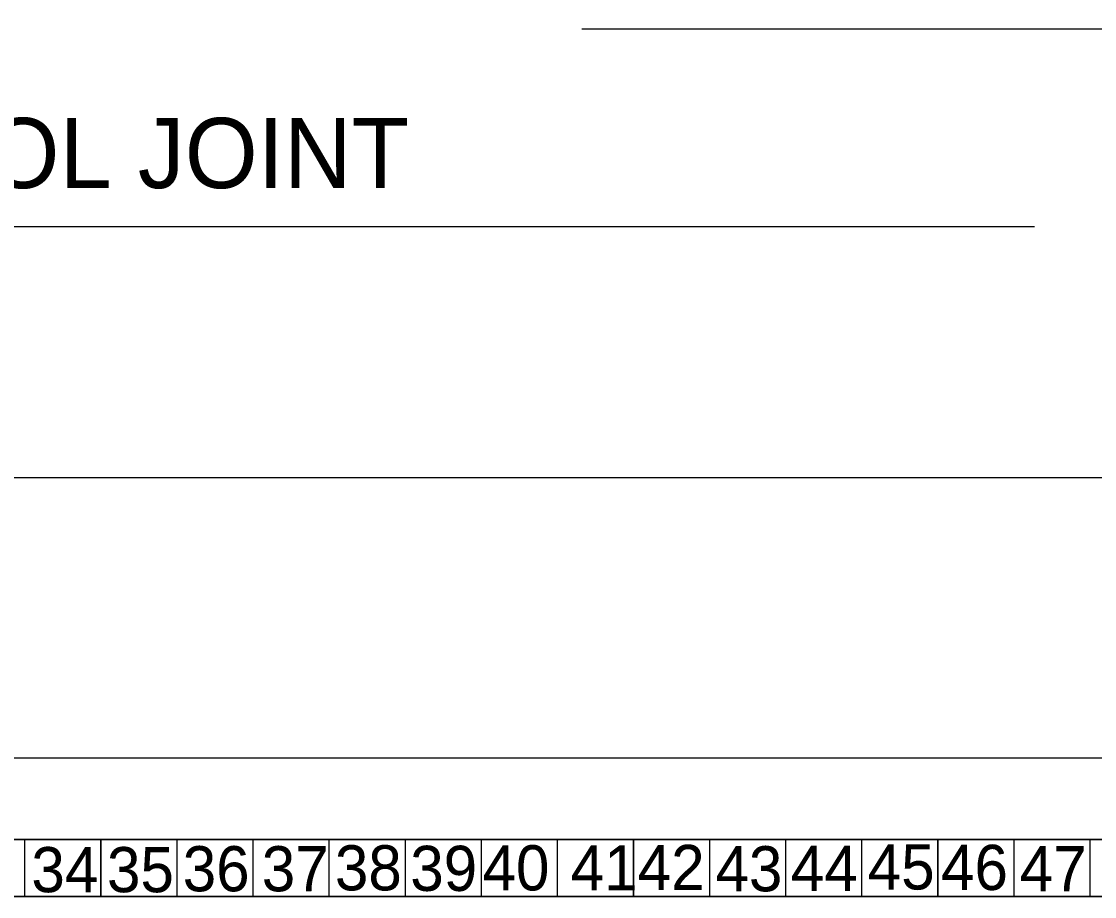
# Model space of a CAD drawing. Extents: x 0 to 2.83, y -0.03 to 1.83.
# Drawn here: x 0.6631 to 0.9019, y -0.0308 to 0.1639 of the extents above; entities that cross this region are included whole.
import ezdxf

# ---------------------------------------------------------------- set-up
doc = ezdxf.new("R2010")
doc.units = 0
for name, color, linetype in [('34', 7, 'Continuous'), ('35', 7, 'Continuous'), ('36', 7, 'Continuous'), ('37', 7, 'Continuous'), ('38', 7, 'Continuous'), ('39', 7, 'Continuous'), ('40', 7, 'Continuous'), ('41', 7, 'Continuous'), ('42', 7, 'Continuous'), ('43', 7, 'Continuous'), ('44', 7, 'Continuous'), ('45', 7, 'Continuous'), ('46', 7, 'Continuous'), ('47', 7, 'Continuous'), ('57', 7, 'Continuous'), ('62', 7, 'Continuous'), ('63', 7, 'Continuous')]:
    doc.layers.add(name, color=color, linetype=linetype)

msp = doc.modelspace()

# ---------------------------------------------------------------- linework, layer by layer
at = {"layer": '57'}
for p, q in [((0.78778, 0.1623), (0.91611, 0.1623)), ((0.22403, 0.11828), (0.88847, 0.11828))]:
    msp.add_line(p, q, dxfattribs=at)
at = {"layer": '62'}
for p, q in [((0.10494, -0.01804), (1.17174, -0.01804)), ((0.10496, -0.0181), (1.17175, -0.0181)), ((0.66374, -0.01804), (0.66374, -0.03074)), ((0.66376, -0.0181), (0.66376, -0.0308)), ((0.68068, -0.01804), (0.68068, -0.03074)), ((0.68069, -0.0181), (0.68069, -0.0308)), ((0.69761, -0.01804), (0.69761, -0.03074)), ((0.69762, -0.0181), (0.69762, -0.0308)), ((0.71454, -0.01804), (0.71454, -0.03074)), ((0.71456, -0.0181), (0.71456, -0.0308)), ((0.73147, -0.01804), (0.73147, -0.03074)), ((0.73149, -0.0181), (0.73149, -0.0308)), ((0.74841, -0.01804), (0.74841, -0.03074)), ((0.74842, -0.0181), (0.74842, -0.0308)), ((0.76534, -0.01804), (0.76534, -0.03074)), ((0.76536, -0.0181), (0.76536, -0.0308)), ((0.78228, -0.01804), (0.78228, -0.03074)), ((0.78229, -0.0181), (0.78229, -0.0308)), ((0.79921, -0.01804), (0.79921, -0.03074)), ((0.79922, -0.0181), (0.79922, -0.0308)), ((0.81614, -0.01804), (0.81614, -0.03074)), ((0.81616, -0.0181), (0.81616, -0.0308)), ((0.83308, -0.01804), (0.83308, -0.03074)), ((0.83309, -0.0181), (0.83309, -0.0308)), ((0.85001, -0.01804), (0.85001, -0.03074)), ((0.85002, -0.0181), (0.85002, -0.0308)), ((0.86694, -0.01804), (0.86694, -0.03074)), ((0.86695, -0.0181), (0.86695, -0.0308)), ((0.88388, -0.01804), (0.88388, -0.03074)), ((0.88389, -0.0181), (0.88389, -0.0308)), ((0.90081, -0.01804), (0.90081, -0.03074)), ((0.90082, -0.0181), (0.90082, -0.0308)), ((0.10494, -0.03074), (1.17174, -0.03074)), ((0.10496, -0.0308), (1.17175, -0.0308))]:
    msp.add_line(p, q, dxfattribs=at)
at = {"layer": '63'}
msp.add_line((2.83333, 0), (0, 0), dxfattribs=at)
msp.add_lwpolyline([(2.72918, 1.77077), (0.10418, 1.77077), (0.10418, 0.06244), (2.72918, 0.06244)], close=True, dxfattribs=at)

# ---------------------------------------------------------------- texts
at = {"layer": '34'}
for p in [(0.66527, -0.02978), (0.66528, -0.02984)]:
    msp.add_text('34', height=0.01, dxfattribs=at).set_placement(p)
at = {"layer": '35'}
for p in [(0.68209, -0.02978), (0.68211, -0.02984)]:
    msp.add_text('35', height=0.01, dxfattribs=at).set_placement(p)
at = {"layer": '36'}
for p in [(0.69895, -0.02958), (0.69896, -0.02964)]:
    msp.add_text('36', height=0.01, dxfattribs=at).set_placement(p)
at = {"layer": '37'}
for p in [(0.71654, -0.02958), (0.71655, -0.02964)]:
    msp.add_text('37', height=0.01, dxfattribs=at).set_placement(p)
at = {"layer": '38'}
for p in [(0.73281, -0.02938), (0.73282, -0.02943)]:
    msp.add_text('38', height=0.01, dxfattribs=at).set_placement(p)
at = {"layer": '39'}
for p in [(0.74958, -0.0295), (0.74959, -0.02955)]:
    msp.add_text('39', height=0.01, dxfattribs=at).set_placement(p)
at = {"layer": '40'}
for p in [(0.76566, -0.02938), (0.76567, -0.02944)]:
    msp.add_text('40', height=0.01, dxfattribs=at).set_placement(p)
at = {"layer": '41'}
for p in [(0.78528, -0.02938), (0.7853, -0.02943)]:
    msp.add_text('41', height=0.01, dxfattribs=at).set_placement(p)
at = {"layer": '42'}
for p in [(0.8002, -0.0293), (0.80022, -0.02936)]:
    msp.add_text('42', height=0.01, dxfattribs=at).set_placement(p)
at = {"layer": '43'}
for p in [(0.8175, -0.02958), (0.81751, -0.02964)]:
    msp.add_text('43', height=0.01, dxfattribs=at).set_placement(p)
at = {"layer": '44'}
for p in [(0.83425, -0.02949), (0.83427, -0.02955)]:
    msp.add_text('44', height=0.01, dxfattribs=at).set_placement(p)
at = {"layer": '45'}
for p in [(0.85139, -0.02918), (0.8514, -0.02924)]:
    msp.add_text('45', height=0.01, dxfattribs=at).set_placement(p)
at = {"layer": '46'}
for p in [(0.8677, -0.02929), (0.86771, -0.02935)]:
    msp.add_text('46', height=0.01, dxfattribs=at).set_placement(p)
at = {"layer": '47'}
for p in [(0.8852, -0.02958), (0.88522, -0.02964)]:
    msp.add_text('47', height=0.01, dxfattribs=at).set_placement(p)
at = {"layer": '57'}
msp.add_text('TYPICAL BOND BEAM DETAIL AT CONTROL JOINT', height=0.015625, dxfattribs=at).set_placement((0.24544, 0.12684))

doc.saveas('drawing.dxf')
